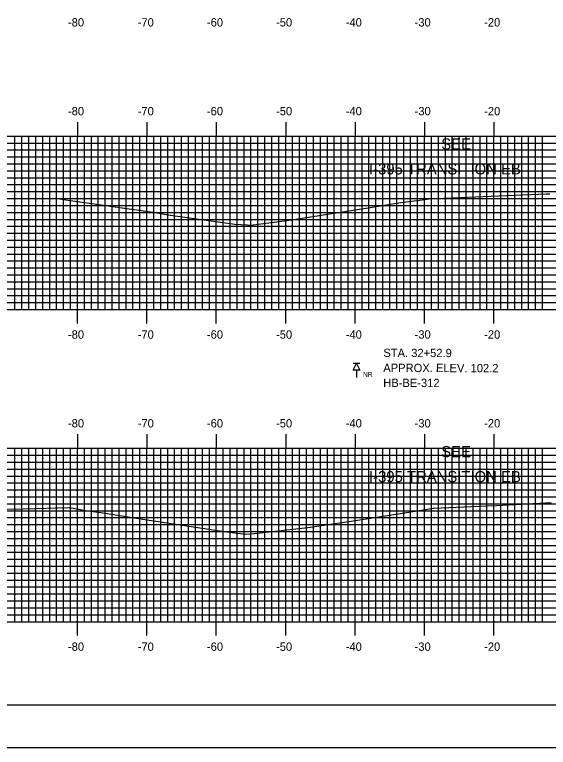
# Model space of a CAD drawing. Extents: x 842569 to 842912, y 363538 to 363758.
# Drawn here: x 842645.4 to 842722.2, y 363537.6 to 363643.2 of the extents above; entities that cross this region are included whole.
import ezdxf

# ---------------------------------------------------------------- set-up
doc = ezdxf.new("R2010")
doc.units = 0
for name, color, linetype in [('ANNOTATION', 7, 'Continuous'), ('BORDER', 7, 'Continuous'), ('BORING - NO REFUSAL', 7, 'Continuous'), ('H_V ANNOTATION', 7, 'Continuous'), ('MAJOR', 7, 'Continuous'), ('MINOR', 7, 'Continuous'), ('PLOT BOUNDARY', 7, 'Continuous'), ('S_Roadway_Centerline', 7, 'Continuous')]:
    doc.layers.add(name, color=color, linetype=linetype)

msp = doc.modelspace()

# ---------------------------------------------------------------- linework, layer by layer
at = {"layer": 'BORDER'}
msp.add_lwpolyline([(842584.8, 363543.72), (842904.8, 363543.72), (842904.8, 363753.72), (842584.8, 363753.72)], close=True, dxfattribs=at)
at = {"layer": 'BORING - NO REFUSAL'}
for p, q in [((842695.08, 363592.92), (842694.12, 363592.92)), ((842694.6, 363591.96), (842694.6, 363590.9))]:
    msp.add_line(p, q, dxfattribs=at)
msp.add_lwpolyline([(842694.6, 363592.92), (842695.08, 363591.96), (842694.12, 363591.96)], close=True, dxfattribs=at)
at = {"layer": 'MAJOR'}
for p, q in [((842654.4, 363627.73), (842654.4, 363625.72)), ((842664.4, 363627.73), (842664.4, 363625.72)), ((842674.4, 363627.73), (842674.4, 363625.72)), ((842684.4, 363627.73), (842684.4, 363625.72)), ((842694.4, 363627.73), (842694.4, 363625.72)), ((842704.4, 363627.73), (842704.4, 363625.72)), ((842714.4, 363627.73), (842714.4, 363625.72)), ((842594.4, 363625.72), (842874.4, 363625.72)), ((842594.4, 363625.72), (842874.4, 363625.72)), ((842654.4, 363600.72), (842654.4, 363625.72)), ((842664.4, 363600.72), (842664.4, 363625.72)), ((842674.4, 363600.72), (842674.4, 363625.72)), ((842684.4, 363600.72), (842684.4, 363625.72)), ((842694.4, 363600.72), (842694.4, 363625.72)), ((842704.4, 363600.72), (842704.4, 363625.72)), ((842714.4, 363600.72), (842714.4, 363625.72)), ((842594.4, 363620.72), (842874.4, 363620.72)), ((842594.4, 363615.72), (842874.4, 363615.72)), ((842594.4, 363610.72), (842874.4, 363610.72)), ((842594.4, 363605.72), (842874.4, 363605.72)), ((842594.4, 363600.72), (842874.4, 363600.72)), ((842594.4, 363600.72), (842874.4, 363600.72)), ((842654.4, 363598.72), (842654.4, 363600.72)), ((842664.4, 363598.72), (842664.4, 363600.72)), ((842674.4, 363598.72), (842674.4, 363600.72)), ((842684.4, 363598.72), (842684.4, 363600.72)), ((842694.4, 363598.72), (842694.4, 363600.72)), ((842704.4, 363598.72), (842704.4, 363600.72)), ((842714.4, 363598.72), (842714.4, 363600.72)), ((842654.4, 363582.73), (842654.4, 363580.72)), ((842664.4, 363582.73), (842664.4, 363580.72)), ((842674.4, 363582.73), (842674.4, 363580.72)), ((842684.4, 363582.73), (842684.4, 363580.72)), ((842694.4, 363582.73), (842694.4, 363580.72)), ((842704.4, 363582.73), (842704.4, 363580.72)), ((842714.4, 363582.73), (842714.4, 363580.72)), ((842594.4, 363580.72), (842874.4, 363580.72)), ((842594.4, 363580.72), (842874.4, 363580.72)), ((842654.4, 363555.72), (842654.4, 363580.72)), ((842664.4, 363555.72), (842664.4, 363580.72)), ((842674.4, 363555.72), (842674.4, 363580.72)), ((842684.4, 363555.72), (842684.4, 363580.72)), ((842694.4, 363555.72), (842694.4, 363580.72)), ((842704.4, 363555.72), (842704.4, 363580.72)), ((842714.4, 363555.72), (842714.4, 363580.72)), ((842594.4, 363575.72), (842874.4, 363575.72)), ((842594.4, 363570.72), (842874.4, 363570.72)), ((842594.4, 363565.72), (842874.4, 363565.72)), ((842594.4, 363560.72), (842874.4, 363560.72)), ((842594.4, 363555.72), (842874.4, 363555.72)), ((842594.4, 363555.72), (842874.4, 363555.72)), ((842654.4, 363553.72), (842654.4, 363555.72)), ((842664.4, 363553.72), (842664.4, 363555.72)), ((842674.4, 363553.72), (842674.4, 363555.72)), ((842684.4, 363553.72), (842684.4, 363555.72)), ((842694.4, 363553.72), (842694.4, 363555.72)), ((842704.4, 363553.72), (842704.4, 363555.72)), ((842714.4, 363553.72), (842714.4, 363555.72))]:
    msp.add_line(p, q, dxfattribs=at)
at = {"layer": 'MINOR'}
for p, q in [((842645.4, 363600.72), (842645.4, 363625.72)), ((842646.4, 363600.72), (842646.4, 363625.72)), ((842647.4, 363600.72), (842647.4, 363625.72)), ((842648.4, 363600.72), (842648.4, 363625.72)), ((842649.4, 363600.72), (842649.4, 363625.72)), ((842650.4, 363600.72), (842650.4, 363625.72)), ((842651.4, 363600.72), (842651.4, 363625.72)), ((842652.4, 363600.72), (842652.4, 363625.72)), ((842653.4, 363600.72), (842653.4, 363625.72)), ((842655.4, 363600.72), (842655.4, 363625.72)), ((842656.4, 363600.72), (842656.4, 363625.72)), ((842657.4, 363600.72), (842657.4, 363625.72)), ((842658.4, 363600.72), (842658.4, 363625.72)), ((842659.4, 363600.72), (842659.4, 363625.72)), ((842660.4, 363600.72), (842660.4, 363625.72)), ((842661.4, 363600.72), (842661.4, 363625.72)), ((842662.4, 363600.72), (842662.4, 363625.72)), ((842663.4, 363600.72), (842663.4, 363625.72)), ((842665.4, 363600.72), (842665.4, 363625.72)), ((842666.4, 363600.72), (842666.4, 363625.72)), ((842667.4, 363600.72), (842667.4, 363625.72)), ((842668.4, 363600.72), (842668.4, 363625.72)), ((842669.4, 363600.72), (842669.4, 363625.72)), ((842670.4, 363600.72), (842670.4, 363625.72)), ((842671.4, 363600.72), (842671.4, 363625.72)), ((842672.4, 363600.72), (842672.4, 363625.72)), ((842673.4, 363600.72), (842673.4, 363625.72)), ((842675.4, 363600.72), (842675.4, 363625.72)), ((842676.4, 363600.72), (842676.4, 363625.72)), ((842677.4, 363600.72), (842677.4, 363625.72)), ((842678.4, 363600.72), (842678.4, 363625.72)), ((842679.4, 363600.72), (842679.4, 363625.72)), ((842680.4, 363600.72), (842680.4, 363625.72)), ((842681.4, 363600.72), (842681.4, 363625.72)), ((842682.4, 363600.72), (842682.4, 363625.72)), ((842683.4, 363600.72), (842683.4, 363625.72)), ((842685.4, 363600.72), (842685.4, 363625.72)), ((842686.4, 363600.72), (842686.4, 363625.72)), ((842687.4, 363600.72), (842687.4, 363625.72)), ((842688.4, 363600.72), (842688.4, 363625.72)), ((842689.4, 363600.72), (842689.4, 363625.72)), ((842690.4, 363600.72), (842690.4, 363625.72)), ((842691.4, 363600.72), (842691.4, 363625.72)), ((842692.4, 363600.72), (842692.4, 363625.72)), ((842693.4, 363600.72), (842693.4, 363625.72)), ((842695.4, 363600.72), (842695.4, 363625.72)), ((842696.4, 363600.72), (842696.4, 363625.72)), ((842697.4, 363600.72), (842697.4, 363625.72)), ((842698.4, 363600.72), (842698.4, 363625.72)), ((842699.4, 363600.72), (842699.4, 363625.72)), ((842700.4, 363600.72), (842700.4, 363625.72)), ((842701.4, 363600.72), (842701.4, 363625.72)), ((842702.4, 363600.72), (842702.4, 363625.72)), ((842703.4, 363600.72), (842703.4, 363625.72)), ((842705.4, 363600.72), (842705.4, 363625.72)), ((842706.4, 363600.72), (842706.4, 363625.72)), ((842707.4, 363600.72), (842707.4, 363625.72)), ((842708.4, 363600.72), (842708.4, 363625.72)), ((842709.4, 363600.72), (842709.4, 363625.72)), ((842710.4, 363600.72), (842710.4, 363625.72)), ((842711.4, 363600.72), (842711.4, 363625.72)), ((842712.4, 363600.72), (842712.4, 363625.72)), ((842713.4, 363600.72), (842713.4, 363625.72)), ((842715.4, 363600.72), (842715.4, 363625.72)), ((842716.4, 363600.72), (842716.4, 363625.72)), ((842717.4, 363600.72), (842717.4, 363625.72)), ((842718.4, 363600.72), (842718.4, 363625.72)), ((842719.4, 363600.72), (842719.4, 363625.72)), ((842720.4, 363600.72), (842720.4, 363625.72)), ((842721.4, 363600.72), (842721.4, 363625.72)), ((842594.4, 363624.72), (842874.4, 363624.72)), ((842594.4, 363623.72), (842874.4, 363623.72)), ((842594.4, 363622.72), (842874.4, 363622.72)), ((842594.4, 363621.72), (842874.4, 363621.72)), ((842594.4, 363619.72), (842874.4, 363619.72)), ((842594.4, 363618.72), (842874.4, 363618.72)), ((842594.4, 363617.72), (842874.4, 363617.72)), ((842594.4, 363616.72), (842874.4, 363616.72)), ((842594.4, 363614.72), (842874.4, 363614.72)), ((842594.4, 363613.72), (842874.4, 363613.72)), ((842594.4, 363612.72), (842874.4, 363612.72)), ((842594.4, 363611.72), (842874.4, 363611.72)), ((842594.4, 363609.72), (842874.4, 363609.72)), ((842594.4, 363608.72), (842874.4, 363608.72)), ((842594.4, 363607.72), (842874.4, 363607.72)), ((842594.4, 363606.72), (842874.4, 363606.72)), ((842594.4, 363604.72), (842874.4, 363604.72)), ((842594.4, 363603.72), (842874.4, 363603.72)), ((842594.4, 363602.72), (842874.4, 363602.72)), ((842594.4, 363601.72), (842874.4, 363601.72)), ((842645.4, 363555.72), (842645.4, 363580.72)), ((842646.4, 363555.72), (842646.4, 363580.72)), ((842647.4, 363555.72), (842647.4, 363580.72)), ((842648.4, 363555.72), (842648.4, 363580.72)), ((842649.4, 363555.72), (842649.4, 363580.72)), ((842650.4, 363555.72), (842650.4, 363580.72)), ((842651.4, 363555.72), (842651.4, 363580.72)), ((842652.4, 363555.72), (842652.4, 363580.72)), ((842653.4, 363555.72), (842653.4, 363580.72)), ((842655.4, 363555.72), (842655.4, 363580.72)), ((842656.4, 363555.72), (842656.4, 363580.72)), ((842657.4, 363555.72), (842657.4, 363580.72)), ((842658.4, 363555.72), (842658.4, 363580.72)), ((842659.4, 363555.72), (842659.4, 363580.72)), ((842660.4, 363555.72), (842660.4, 363580.72)), ((842661.4, 363555.72), (842661.4, 363580.72)), ((842662.4, 363555.72), (842662.4, 363580.72)), ((842663.4, 363555.72), (842663.4, 363580.72)), ((842665.4, 363555.72), (842665.4, 363580.72)), ((842666.4, 363555.72), (842666.4, 363580.72)), ((842667.4, 363555.72), (842667.4, 363580.72)), ((842668.4, 363555.72), (842668.4, 363580.72)), ((842669.4, 363555.72), (842669.4, 363580.72)), ((842670.4, 363555.72), (842670.4, 363580.72)), ((842671.4, 363555.72), (842671.4, 363580.72)), ((842672.4, 363555.72), (842672.4, 363580.72)), ((842673.4, 363555.72), (842673.4, 363580.72)), ((842675.4, 363555.72), (842675.4, 363580.72)), ((842676.4, 363555.72), (842676.4, 363580.72)), ((842677.4, 363555.72), (842677.4, 363580.72)), ((842678.4, 363555.72), (842678.4, 363580.72)), ((842679.4, 363555.72), (842679.4, 363580.72)), ((842680.4, 363555.72), (842680.4, 363580.72)), ((842681.4, 363555.72), (842681.4, 363580.72)), ((842682.4, 363555.72), (842682.4, 363580.72)), ((842683.4, 363555.72), (842683.4, 363580.72)), ((842685.4, 363555.72), (842685.4, 363580.72)), ((842686.4, 363555.72), (842686.4, 363580.72)), ((842687.4, 363555.72), (842687.4, 363580.72)), ((842688.4, 363555.72), (842688.4, 363580.72)), ((842689.4, 363555.72), (842689.4, 363580.72)), ((842690.4, 363555.72), (842690.4, 363580.72)), ((842691.4, 363555.72), (842691.4, 363580.72)), ((842692.4, 363555.72), (842692.4, 363580.72)), ((842693.4, 363555.72), (842693.4, 363580.72)), ((842695.4, 363555.72), (842695.4, 363580.72)), ((842696.4, 363555.72), (842696.4, 363580.72)), ((842697.4, 363555.72), (842697.4, 363580.72)), ((842698.4, 363555.72), (842698.4, 363580.72)), ((842699.4, 363555.72), (842699.4, 363580.72)), ((842700.4, 363555.72), (842700.4, 363580.72)), ((842701.4, 363555.72), (842701.4, 363580.72)), ((842702.4, 363555.72), (842702.4, 363580.72)), ((842703.4, 363555.72), (842703.4, 363580.72)), ((842705.4, 363555.72), (842705.4, 363580.72)), ((842706.4, 363555.72), (842706.4, 363580.72)), ((842707.4, 363555.72), (842707.4, 363580.72)), ((842708.4, 363555.72), (842708.4, 363580.72)), ((842709.4, 363555.72), (842709.4, 363580.72)), ((842710.4, 363555.72), (842710.4, 363580.72)), ((842711.4, 363555.72), (842711.4, 363580.72)), ((842712.4, 363555.72), (842712.4, 363580.72)), ((842713.4, 363555.72), (842713.4, 363580.72)), ((842715.4, 363555.72), (842715.4, 363580.72)), ((842716.4, 363555.72), (842716.4, 363580.72)), ((842717.4, 363555.72), (842717.4, 363580.72)), ((842718.4, 363555.72), (842718.4, 363580.72)), ((842719.4, 363555.72), (842719.4, 363580.72)), ((842720.4, 363555.72), (842720.4, 363580.72)), ((842721.4, 363555.72), (842721.4, 363580.72)), ((842594.4, 363579.72), (842874.4, 363579.72)), ((842594.4, 363578.72), (842874.4, 363578.72)), ((842594.4, 363577.72), (842874.4, 363577.72)), ((842594.4, 363576.72), (842874.4, 363576.72)), ((842594.4, 363574.72), (842874.4, 363574.72)), ((842594.4, 363573.72), (842874.4, 363573.72)), ((842594.4, 363572.72), (842874.4, 363572.72)), ((842594.4, 363571.72), (842874.4, 363571.72)), ((842594.4, 363569.72), (842874.4, 363569.72)), ((842594.4, 363568.72), (842874.4, 363568.72)), ((842594.4, 363567.72), (842874.4, 363567.72)), ((842594.4, 363566.72), (842874.4, 363566.72)), ((842594.4, 363564.72), (842874.4, 363564.72)), ((842594.4, 363563.72), (842874.4, 363563.72)), ((842594.4, 363562.72), (842874.4, 363562.72)), ((842594.4, 363561.72), (842874.4, 363561.72)), ((842594.4, 363559.72), (842874.4, 363559.72)), ((842594.4, 363558.72), (842874.4, 363558.72)), ((842594.4, 363557.72), (842874.4, 363557.72)), ((842594.4, 363556.72), (842874.4, 363556.72))]:
    msp.add_line(p, q, dxfattribs=at)
at = {"layer": 'PLOT BOUNDARY'}
msp.add_lwpolyline([(842568.61, 363537.6), (842908.61, 363537.6), (842908.61, 363757.6), (842568.61, 363757.6)], close=True, dxfattribs=at)
at = {"layer": 'S_Roadway_Centerline'}
for points in [[(842641.63, 363616.69), (842645.37, 363616.74), (842651.88, 363616.69), (842652.74, 363616.55), (842665.24, 363614.74), (842667.8, 363614.34), (842677.06, 363613.02), (842678.87, 363612.95), (842679.34, 363612.87), (842684.61, 363613.57), (842696.28, 363615.36), (842701, 363616.14), (842704.05, 363616.55), (842705.07, 363616.68), (842706.05, 363616.72), (842721.97, 363617.39), (842722.43, 363617.41)], [(842642.61, 363571.95), (842646.59, 363572.01), (842653.26, 363572.16), (842655.56, 363571.75), (842657.77, 363571.44), (842664.73, 363570.34), (842675.88, 363568.66), (842678.64, 363568.35), (842679.84, 363568.41), (842687.58, 363569.29), (842693.84, 363570.2), (842703.94, 363571.8), (842705.68, 363572.08), (842705.7, 363572.09), (842713.37, 363572.4), (842714.75, 363572.47), (842722.63, 363572.9)]]:
    msp.add_lwpolyline(points, dxfattribs=at)

# ---------------------------------------------------------------- texts
at = {"layer": 'ANNOTATION'}
for s, p in [('SEE', (842706.81, 363623.79)), ('I-395 TRANSITION EB', (842696.4, 363620.19)), ('SEE', (842706.81, 363579.43)), ('I-395 TRANSITION EB', (842696.4, 363575.83))]:
    msp.add_text(s, height=1.6, dxfattribs=at).set_placement(p)
at = {"layer": 'BORING - NO REFUSAL'}
for s, p in [('STA. 32+52.9', (842698.47, 363593.88)), ('APPROX. ELEV. 102.2', (842698.46, 363591.72)), ('HB-BE-312', (842698.45, 363589.56))]:
    msp.add_text(s, height=1.2, rotation=359.8142, dxfattribs=at).set_placement(p)
msp.add_text('NR', height=0.7, dxfattribs=at).set_placement((842695.53, 363591.01))
at = {"layer": 'H_V ANNOTATION'}
for s, p in [('-80', (842653.03, 363641.52)), ('-70', (842663.08, 363641.52)), ('-60', (842673.05, 363641.52)), ('-50', (842683.01, 363641.52)), ('-40', (842693.05, 363641.52)), ('-30', (842702.97, 363641.52)), ('-20', (842712.99, 363641.52)), ('-80', (842653.03, 363628.72)), ('-70', (842663.08, 363628.72)), ('-60', (842673.05, 363628.72)), ('-50', (842683.01, 363628.72)), ('-40', (842693.05, 363628.72)), ('-30', (842702.97, 363628.72)), ('-20', (842712.99, 363628.72)), ('-80', (842653.03, 363596.52)), ('-70', (842663.08, 363596.52)), ('-60', (842673.05, 363596.52)), ('-50', (842683.01, 363596.52)), ('-40', (842693.05, 363596.52)), ('-30', (842702.97, 363596.52)), ('-20', (842712.99, 363596.52)), ('-80', (842653.03, 363583.72)), ('-70', (842663.08, 363583.72)), ('-60', (842673.05, 363583.72)), ('-50', (842683.01, 363583.72)), ('-40', (842693.05, 363583.72)), ('-30', (842702.97, 363583.72)), ('-20', (842712.99, 363583.72)), ('-80', (842653.03, 363551.52)), ('-70', (842663.08, 363551.52)), ('-60', (842673.05, 363551.52)), ('-50', (842683.01, 363551.52)), ('-40', (842693.05, 363551.52)), ('-30', (842702.97, 363551.52)), ('-20', (842712.99, 363551.52))]:
    msp.add_text(s, height=1.2, dxfattribs=at).set_placement(p)

doc.saveas('drawing.dxf')
